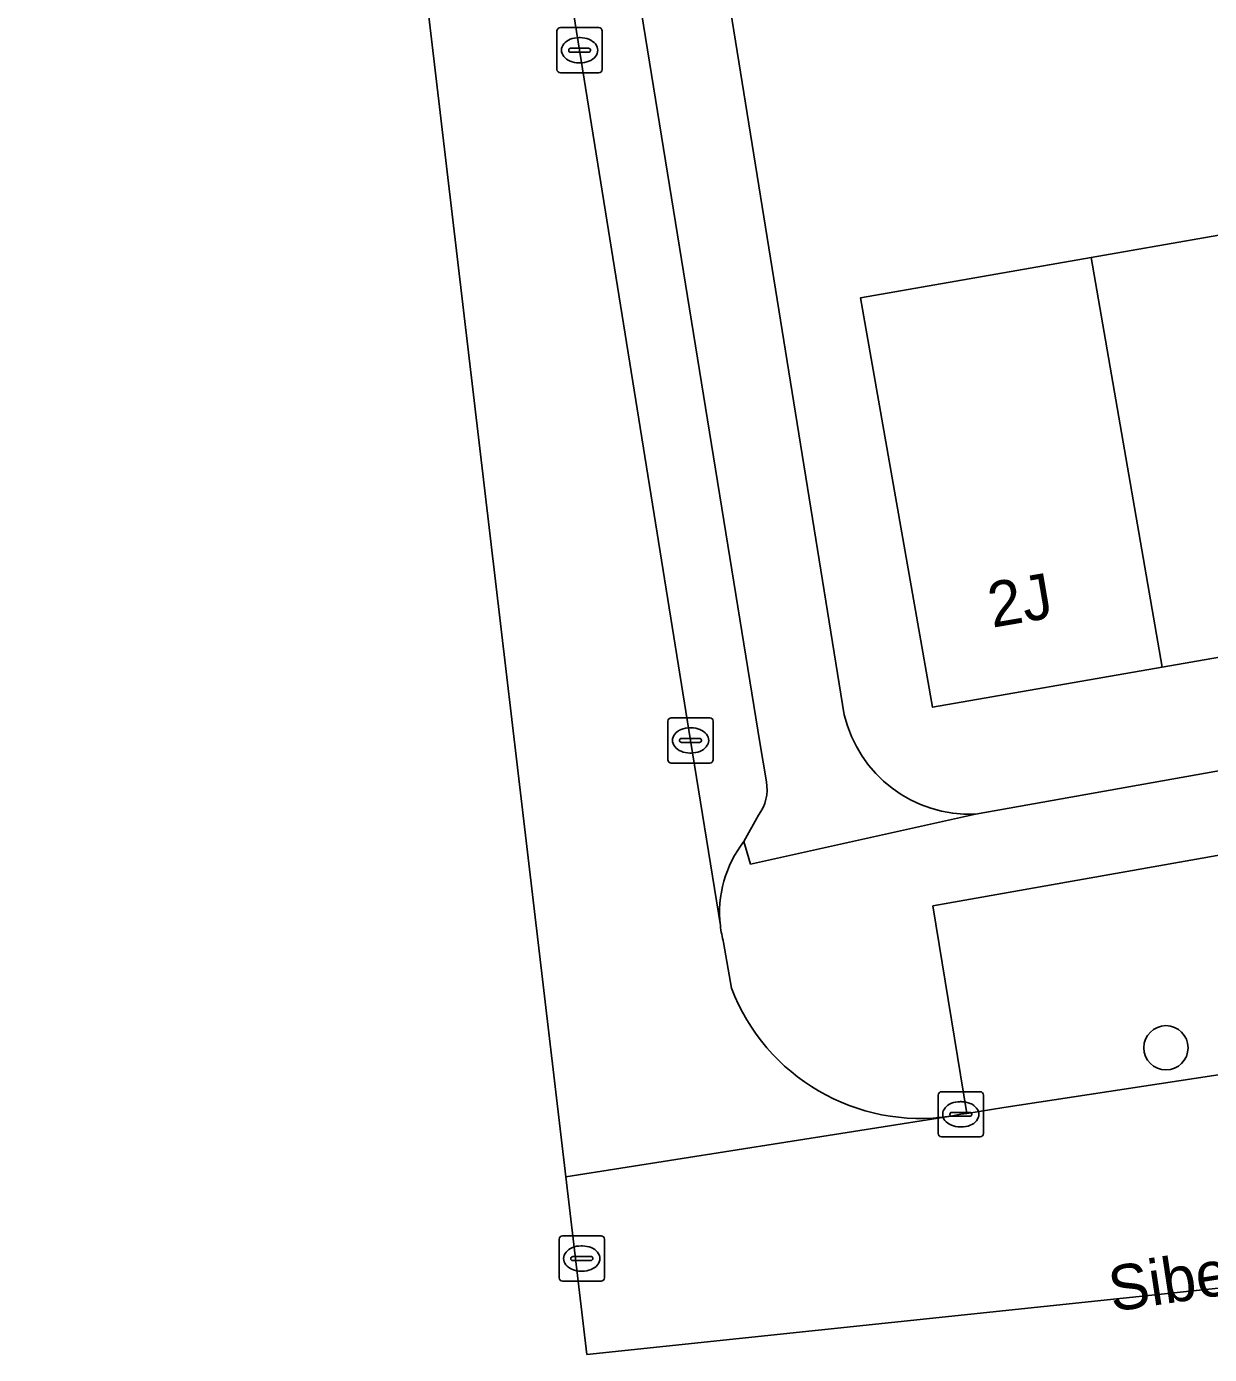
# Model space of a CAD drawing. Extents: x 160157 to 160921, y 381516 to 382045.
# Drawn here: x 160413.75 to 160439.93, y 381516.39 to 381545.76 of the extents above; entities that cross this region are included whole.
import ezdxf

# ---------------------------------------------------------------- set-up
doc = ezdxf.new("R2010")
doc.units = 0
for name, color, linetype in [('IMGEO_Boom', 7, 'Continuous'), ('IMGEO_Erf', 7, 'Continuous'), ('IMGEO_Groenvoorziening', 7, 'Continuous'), ('IMGEO_Kolk', 7, 'Continuous'), ('IMGEO_Openbare_ruimte_label', 7, 'Continuous'), ('IMGEO_Pand', 7, 'Continuous'), ('IMGEO_Pand_nummerreeks', 7, 'Continuous'), ('IMGEO_Parkeervlak_open', 7, 'Continuous'), ('IMGEO_Rijbaan_lokaal_gesloten', 7, 'Continuous'), ('IMGEO_Rijbaan_lokaal_open', 7, 'Continuous'), ('IMGEO_Rioolput', 7, 'Continuous'), ('IMGEO_Voetpad_open', 7, 'Continuous')]:
    doc.layers.add(name, color=color, linetype=linetype)

msp = doc.modelspace()

# ---------------------------------------------------------------- linework, layer by layer
at = {"layer": 'IMGEO_Boom'}
msp.add_circle((160438.968, 381523.175), 0.489, dxfattribs=at)
at = {"layer": 'IMGEO_Erf'}
for points in [[(160426.627, 381562.902), (160431.85, 381530.539)], [(160474.25, 381535.884), (160479.661, 381537.702), (160479.49, 381538.693), (160474.414, 381537.806), (160469.338, 381536.918), (160464.261, 381536.031), (160459.185, 381535.143), (160454.109, 381534.256), (160449.033, 381533.368), (160443.956, 381532.481), (160438.88, 381531.593), (160433.804, 381530.706), (160432.209, 381539.762), (160437.314, 381540.654), (160442.369, 381541.536), (160447.476, 381542.428), (160452.53, 381543.311), (160457.61, 381544.198), (160462.69, 381545.085), (160467.771, 381545.973), (160472.851, 381546.86), (160477.931, 381547.747), (160476.88, 381554.468)], [(160434.753, 381528.34), (160465.414, 381533.807)]]:
    msp.add_lwpolyline(points, dxfattribs=at)
msp.add_arc((160434.632, 381531.195), 2.858, 193.2771, 272.4356, dxfattribs=at)
at = {"layer": 'IMGEO_Groenvoorziening'}
msp.add_lwpolyline([(160441.794, 381525.46), (160443.915, 381525.784), (160443.558, 381528.038), (160433.809, 381526.312), (160434.562, 381521.724), (160435.377, 381521.853), (160441.143, 381522.733)], dxfattribs=at)
at = {"layer": 'IMGEO_Kolk'}
for p, q in [((160425.492, 381544.812), (160425.492, 381545.664)), ((160425.567, 381545.738), (160426.419, 381545.738)), ((160426.493, 381545.664), (160426.493, 381544.812)), ((160425.794, 381545.281), (160426.192, 381545.281)), ((160425.98, 381545.518), (160426.005, 381545.518)), ((160425.751, 381545.232), (160425.751, 381545.244)), ((160426.189, 381545.195), (160425.791, 381545.195)), ((160426.235, 381545.244), (160426.235, 381545.232)), ((160426.419, 381544.738), (160425.567, 381544.738)), ((160426.003, 381544.958), (160425.978, 381544.958)), ((160427.947, 381529.547), (160427.947, 381530.399)), ((160428.022, 381530.473), (160428.874, 381530.473)), ((160428.948, 381530.399), (160428.948, 381529.547)), ((160428.249, 381530.016), (160428.647, 381530.016)), ((160428.435, 381530.253), (160428.46, 381530.253)), ((160428.206, 381529.967), (160428.206, 381529.979)), ((160428.644, 381529.93), (160428.246, 381529.93)), ((160428.69, 381529.979), (160428.69, 381529.967)), ((160428.874, 381529.473), (160428.022, 381529.473)), ((160428.458, 381529.693), (160428.433, 381529.693)), ((160433.927, 381521.277), (160433.927, 381522.129)), ((160434.002, 381522.203), (160434.854, 381522.203)), ((160434.928, 381522.129), (160434.928, 381521.277)), ((160434.415, 381521.983), (160434.44, 381521.983)), ((160434.186, 381521.697), (160434.186, 381521.709)), ((160434.624, 381521.66), (160434.226, 381521.66)), ((160434.229, 381521.746), (160434.627, 381521.746)), ((160434.67, 381521.709), (160434.67, 381521.697)), ((160434.854, 381521.203), (160434.002, 381521.203)), ((160434.438, 381521.423), (160434.413, 381521.423))]:
    msp.add_line(p, q, dxfattribs=at)
for points in [[(160425.492, 381544.812), (160425.492, 381545.664)], [(160425.567, 381545.738), (160426.419, 381545.738)], [(160426.493, 381545.664), (160426.493, 381544.812)], [(160426.419, 381544.738), (160425.567, 381544.738)], [(160427.947, 381529.547), (160427.947, 381530.399)], [(160428.022, 381530.473), (160428.874, 381530.473)], [(160428.948, 381530.399), (160428.948, 381529.547)], [(160428.874, 381529.473), (160428.022, 381529.473)], [(160433.927, 381521.277), (160433.927, 381522.129)], [(160434.002, 381522.203), (160434.854, 381522.203)], [(160434.928, 381522.129), (160434.928, 381521.277)], [(160434.854, 381521.203), (160434.002, 381521.203)]]:
    msp.add_lwpolyline(points, dxfattribs=at)
for centre, radius, start, end in [((160425.569, 381545.662), 0.0765, 91.552, 178.448), ((160425.569, 381545.662), 0.0765, 91.552, 178.448), ((160426.417, 381545.662), 0.0765, 1.552, 88.448), ((160426.417, 381545.662), 0.0765, 1.552, 88.448), ((160425.791, 381545.241), 0.0403, 85.8775, 175.7526), ((160426.196, 381545.243), 0.0386, 1.7309, 96.639), ((160425.788, 381545.231), 0.0366, 178.938, 274.7102), ((160426.192, 381545.238), 0.043, 264.8664, 352.4533), ((160425.569, 381544.814), 0.0765, 181.552, 268.448), ((160425.569, 381544.814), 0.0765, 181.552, 268.448), ((160426.417, 381544.814), 0.0765, 271.552, 358.448), ((160426.417, 381544.814), 0.0765, 271.552, 358.448), ((160428.024, 381530.397), 0.0765, 91.552, 178.448), ((160428.024, 381530.397), 0.0765, 91.552, 178.448), ((160428.872, 381530.397), 0.0765, 1.552, 88.448), ((160428.872, 381530.397), 0.0765, 1.552, 88.448), ((160428.246, 381529.976), 0.0403, 85.8775, 175.7526), ((160428.651, 381529.978), 0.0386, 1.7309, 96.639), ((160428.243, 381529.966), 0.0366, 178.938, 274.7102), ((160428.647, 381529.973), 0.043, 264.8664, 352.4533), ((160428.024, 381529.549), 0.0765, 181.552, 268.448), ((160428.024, 381529.549), 0.0765, 181.552, 268.448), ((160428.872, 381529.549), 0.0765, 271.552, 358.448), ((160428.872, 381529.549), 0.0765, 271.552, 358.448), ((160434.004, 381522.127), 0.0765, 91.552, 178.448), ((160434.004, 381522.127), 0.0765, 91.552, 178.448), ((160434.852, 381522.127), 0.0765, 1.552, 88.448), ((160434.852, 381522.127), 0.0765, 1.552, 88.448), ((160434.226, 381521.706), 0.0403, 85.8775, 175.7526), ((160434.223, 381521.696), 0.0366, 178.938, 274.7102), ((160434.627, 381521.703), 0.043, 264.8664, 352.4533), ((160434.631, 381521.708), 0.0386, 1.7309, 96.639), ((160434.004, 381521.279), 0.0765, 181.552, 268.448), ((160434.004, 381521.279), 0.0765, 181.552, 268.448), ((160434.852, 381521.279), 0.0765, 271.552, 358.448), ((160434.852, 381521.279), 0.0765, 271.552, 358.448)]:
    msp.add_arc(centre, radius, start, end, dxfattribs=at)
for centre, major_axis, ratio, start_param, end_param in [((160425.979, 381545.238), (-0.387, 0.002), 0.722429, 4.712389, 7.853982), ((160426.004, 381545.238), (-0.39, 0.002), 0.717154, 1.570796, 4.712389), ((160428.434, 381529.973), (-0.387, 0.002), 0.722429, 4.712389, 7.853982), ((160428.459, 381529.973), (-0.39, 0.002), 0.717154, 1.570796, 4.712389), ((160434.414, 381521.703), (-0.387, 0.002), 0.722429, 4.712389, 7.853982), ((160434.439, 381521.703), (-0.39, 0.002), 0.717154, 1.570796, 4.712389)]:
    msp.add_ellipse(centre, major_axis=major_axis, ratio=ratio, start_param=start_param, end_param=end_param, dxfattribs=at)
at = {"layer": 'IMGEO_Pand'}
for points in [[(160442.369, 381541.536), (160437.314, 381540.654), (160438.88, 381531.593), (160443.956, 381532.481)], [(160437.314, 381540.654), (160432.209, 381539.762), (160433.804, 381530.706), (160438.88, 381531.593)]]:
    msp.add_lwpolyline(points, close=True, dxfattribs=at)
at = {"layer": 'IMGEO_Parkeervlak_open'}
for points in [[(160422.828, 381564.957), (160424.108, 381556.964), (160425.993, 381545.238), (160428.448, 381529.973), (160429.107, 381525.876)], [(160430.126, 381529.058), (160429.98, 381529.925), (160424.689, 381562.531)], [(160429.629, 381527.737), (160429.951, 381528.319)]]:
    msp.add_lwpolyline(points, dxfattribs=at)
for centre, radius, start, end in [((160429.199, 381528.887), 0.942, 322.9094, 10.4454), ((160431.641, 381526.169), 2.551, 142.0653, 186.5976)]:
    msp.add_arc(centre, radius, start, end, dxfattribs=at)
at = {"layer": 'IMGEO_Rijbaan_lokaal_gesloten'}
for points in [[(160513.931, 381535.305), (160510.743, 381534.735), (160508.639, 381534.334), (160500, 381532.746), (160494.487, 381531.742), (160493.5, 381531.587), (160480.817, 381529.226), (160478.444, 381528.805), (160465.728, 381526.595), (160463.815, 381526.282), (160451.015, 381524.259), (160448.992, 381523.939), (160441.143, 381522.733), (160435.377, 381521.853), (160434.562, 381521.724), (160434.428, 381521.703), (160434.207, 381521.662), (160425.691, 381520.323)], [(160425.691, 381520.323), (160426.156, 381516.392), (160519.058, 381526.148), (160520.971, 381526.488), (160519.788, 381529.587), (160502.108, 381528.076)]]:
    msp.add_lwpolyline(points, dxfattribs=at)
at = {"layer": 'IMGEO_Rijbaan_lokaal_open'}
for points in [[(160315.96, 381633.935), (160314.492, 381631.674), (160336.288, 381617.43), (160360.481, 381601.619), (160420.655, 381562.912), (160425.691, 381520.323)], [(160429.107, 381525.876), (160428.448, 381529.973), (160425.993, 381545.238), (160424.108, 381556.964), (160422.828, 381564.957), (160416.716, 381568.924), (160409.388, 381573.68), (160408.723, 381574.112), (160407.685, 381574.769), (160404.488, 381576.764), (160394.652, 381583.11), (160389.591, 381586.361), (160379.608, 381592.774), (160374.562, 381596.051), (160364.374, 381602.611), (160361.213, 381604.662), (160316.781, 381633.231)], [(160429.352, 381524.49), (160429.179, 381525.5)], [(160425.691, 381520.323), (160434.207, 381521.662)]]:
    msp.add_lwpolyline(points, dxfattribs=at)
for centre, radius, start, end in [((160431.687, 381526.175), 2.597, 186.6138, 195.0668), ((160433.538, 381526.095), 4.483, 200.9742, 278.5848)]:
    msp.add_arc(centre, radius, start, end, dxfattribs=at)
at = {"layer": 'IMGEO_Rioolput'}
for p, q in [((160425.54, 381518.087), (160425.54, 381518.939)), ((160425.615, 381519.013), (160426.467, 381519.013)), ((160426.541, 381518.939), (160426.541, 381518.087)), ((160425.842, 381518.556), (160426.24, 381518.556)), ((160426.028, 381518.793), (160426.053, 381518.793)), ((160425.799, 381518.507), (160425.799, 381518.519)), ((160426.237, 381518.47), (160425.839, 381518.47)), ((160426.283, 381518.519), (160426.283, 381518.507)), ((160426.467, 381518.013), (160425.615, 381518.013)), ((160426.051, 381518.233), (160426.026, 381518.233))]:
    msp.add_line(p, q, dxfattribs=at)
for points in [[(160425.54, 381518.087), (160425.54, 381518.939)], [(160425.615, 381519.013), (160426.467, 381519.013)], [(160426.541, 381518.939), (160426.541, 381518.087)], [(160426.467, 381518.013), (160425.615, 381518.013)]]:
    msp.add_lwpolyline(points, dxfattribs=at)
for centre, radius, start, end in [((160425.617, 381518.937), 0.0765, 91.552, 178.448), ((160425.617, 381518.937), 0.0765, 91.552, 178.448), ((160426.465, 381518.937), 0.0765, 1.552, 88.448), ((160426.465, 381518.937), 0.0765, 1.552, 88.448), ((160425.839, 381518.516), 0.0403, 85.8775, 175.7526), ((160426.244, 381518.518), 0.0386, 1.7309, 96.639), ((160425.836, 381518.506), 0.0366, 178.938, 274.7102), ((160426.24, 381518.513), 0.043, 264.8664, 352.4533), ((160425.617, 381518.089), 0.0765, 181.552, 268.448), ((160425.617, 381518.089), 0.0765, 181.552, 268.448), ((160426.465, 381518.089), 0.0765, 271.552, 358.448), ((160426.465, 381518.089), 0.0765, 271.552, 358.448)]:
    msp.add_arc(centre, radius, start, end, dxfattribs=at)
for centre, major_axis, ratio, start_param, end_param in [((160426.027, 381518.513), (-0.387, 0.002), 0.722429, 4.712389, 7.853982), ((160426.052, 381518.513), (-0.39, 0.002), 0.717154, 1.570796, 4.712389)]:
    msp.add_ellipse(centre, major_axis=major_axis, ratio=ratio, start_param=start_param, end_param=end_param, dxfattribs=at)
at = {"layer": 'IMGEO_Voetpad_open'}
for points in [[(160431.85, 381530.539), (160426.627, 381562.902)], [(160424.689, 381562.531), (160429.98, 381529.925), (160430.126, 381529.058)], [(160465.414, 381533.807), (160434.753, 381528.34), (160429.777, 381527.238), (160429.629, 381527.737)], [(160434.207, 381521.662), (160434.428, 381521.703), (160434.562, 381521.724), (160433.809, 381526.312), (160443.558, 381528.038), (160443.915, 381525.784), (160441.794, 381525.46), (160441.906, 381524.701), (160447.67, 381525.607), (160447.553, 381526.337), (160445.431, 381526.009), (160445.073, 381528.319), (160455.824, 381530.238), (160456.241, 381527.696), (160451.637, 381526.942), (160451.772, 381526.212), (160462.466, 381527.952), (160462.335, 381528.674), (160457.757, 381527.949), (160457.326, 381530.511), (160466.355, 381532.125)], [(160429.951, 381528.319), (160429.629, 381527.737), (160429.777, 381527.238), (160434.753, 381528.34)], [(160429.179, 381525.5), (160429.352, 381524.49)]]:
    msp.add_lwpolyline(points, dxfattribs=at)
for centre, radius, start, end in [((160434.632, 381531.195), 2.858, 193.2771, 272.4356), ((160429.199, 381528.887), 0.942, 322.9094, 10.4454), ((160431.641, 381526.169), 2.551, 142.0653, 186.5976), ((160431.687, 381526.175), 2.597, 186.6138, 195.0668), ((160433.538, 381526.095), 4.483, 200.9742, 278.5848)]:
    msp.add_arc(centre, radius, start, end, dxfattribs=at)

# ---------------------------------------------------------------- texts
at = {"layer": 'IMGEO_Openbare_ruimte_label'}
msp.add_text('Sibeliuslaan', height=1, rotation=8.6242, dxfattribs=at).set_placement((160437.78, 381517.332))
at = {"layer": 'IMGEO_Pand_nummerreeks'}
msp.add_text('2J', height=1, rotation=9.7174, dxfattribs=at).set_placement((160435.123, 381532.463))

doc.saveas('drawing.dxf')
